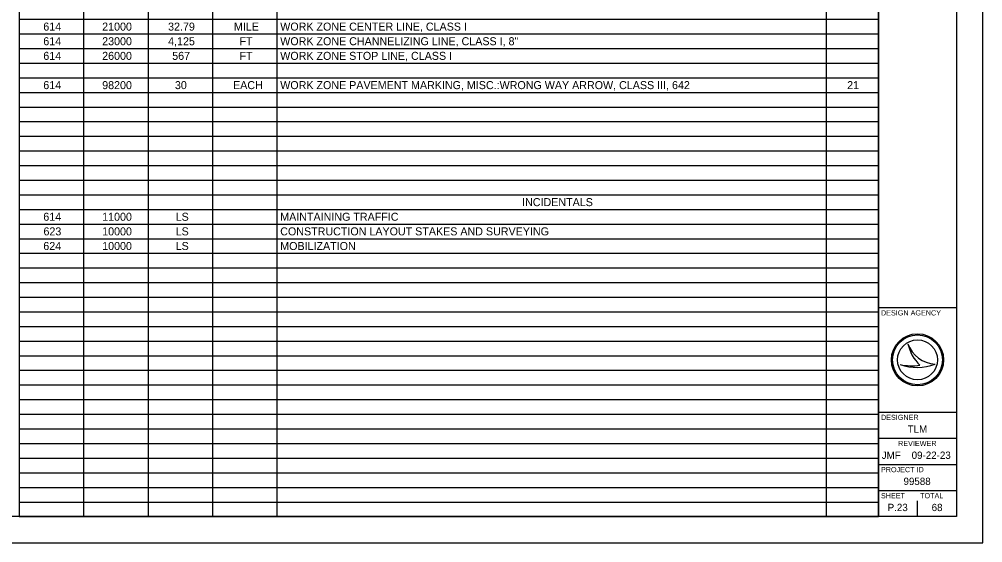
# Model space of a CAD drawing. Extents: x 0 to 34, y 0 to 22.
# Drawn here: x 15.54 to 34, y 0 to 10.02 of the extents above; entities that cross this region are included whole.
import ezdxf

# ---------------------------------------------------------------- set-up
doc = ezdxf.new("R2010")
doc.units = 0
for name, color, linetype in [('SH_Border', 7, 'Continuous'), ('SH_Cut_Line', 7, 'Continuous'), ('SH_Data', 7, 'Continuous'), ('SH_Text', 7, 'Continuous')]:
    doc.layers.add(name, color=color, linetype=linetype)

msp = doc.modelspace()

# ---------------------------------------------------------------- linework, layer by layer
at = {"layer": 'SH_Border'}
for p, q in [((32, 0.5), (32, 21.5)), ((32, 4.5), (33.5, 4.5)), ((32, 2.5), (33.5, 2.5)), ((32, 2), (33.5, 2)), ((32, 1.5), (33.5, 1.5)), ((32, 1), (33.5, 1))]:
    msp.add_line(p, q, dxfattribs=at)
msp.add_lwpolyline([(1.5, 21.5), (33.5, 21.5), (33.5, 0.5), (1.5, 0.5)], close=True, dxfattribs=at)
at = {"layer": 'SH_Cut_Line'}
msp.add_lwpolyline([(0, 0), (34, 0), (34, 22), (0, 22)], close=True, dxfattribs=at)
at = {"layer": 'SH_Data'}
for p, q in [((32.567, 3.81), (32.567, 3.81)), ((32.417, 3.41), (32.417, 3.41)), ((32.75, 3.5), (32.75, 3.5)), ((33.087, 3.419), (33.087, 3.419)), ((32.75, 0.5), (32.75, 0.8)), ((32.375, 0.675), (32.375, 0.675))]:
    msp.add_line(p, q, dxfattribs=at)
for radius in [0.5, 0.477, 0.477, 0.382]:
    msp.add_circle((32.75, 3.5), radius, dxfattribs=at)
for centre, radius, start, end in [((33.116, 3.998), 0.58, 198.9257, 198.9319), ((33.347, 3.97), 0.796, 191.6379, 191.6421), ((33.116, 3.998), 0.58, 198.9319, 267.1657), ((33.347, 3.97), 0.796, 191.6421, 226.0947), ((32.739, 4.37), 1.013, 251.4576, 290.0832), ((32.648, 4.654), 1.266, 259.4964, 259.4995), ((32.739, 4.37), 1.013, 251.4527, 251.4576), ((32.648, 4.654), 1.266, 259.4995, 276.6672)]:
    msp.add_arc(centre, radius, start, end, dxfattribs=at)
at = {"layer": 'SH_Text'}
for p, q in [((15.537, 10.3), (15.537, 10.02)), ((16.771, 10.3), (16.771, 10.02)), ((18.005, 10.3), (18.005, 10.02)), ((19.239, 10.3), (19.239, 10.02)), ((20.473, 10.3), (20.473, 10.02)), ((31.001, 10.3), (31.001, 10.02)), ((32.004, 10.3), (32.004, 10.02)), ((15.537, 10.02), (18.005, 10.02)), ((15.537, 10.02), (15.537, 9.74)), ((16.771, 10.02), (16.771, 9.74)), ((18.005, 10.02), (19.239, 10.02)), ((18.005, 10.02), (18.005, 9.74)), ((19.239, 10.02), (32.004, 10.02)), ((19.239, 10.02), (19.239, 9.74)), ((20.473, 10.02), (20.473, 9.74)), ((31.001, 10.02), (31.001, 9.74)), ((32.004, 10.02), (32.004, 9.74)), ((15.537, 9.74), (18.005, 9.74)), ((15.537, 9.74), (15.537, 8.9)), ((16.771, 9.74), (16.771, 8.9)), ((18.005, 9.74), (19.239, 9.74)), ((18.005, 9.74), (18.005, 8.9)), ((19.239, 9.74), (32.004, 9.74)), ((19.239, 9.74), (19.239, 8.9)), ((20.473, 9.74), (20.473, 8.9)), ((31.001, 9.74), (31.001, 8.9)), ((32.004, 9.74), (32.004, 8.9)), ((15.537, 9.46), (18.005, 9.46)), ((18.005, 9.46), (19.239, 9.46)), ((19.239, 9.46), (32.004, 9.46)), ((15.537, 9.18), (18.005, 9.18)), ((18.005, 9.18), (19.239, 9.18)), ((19.239, 9.18), (32.004, 9.18)), ((15.537, 8.9), (18.005, 8.9)), ((15.537, 8.9), (15.537, 8.34)), ((16.771, 8.9), (16.771, 8.34)), ((18.005, 8.9), (19.239, 8.9)), ((18.005, 8.9), (18.005, 8.34)), ((19.239, 8.9), (32.004, 8.9)), ((19.239, 8.9), (19.239, 8.34)), ((20.473, 8.9), (20.473, 8.34)), ((31.001, 8.9), (31.001, 8.34)), ((32.004, 8.9), (32.004, 8.34)), ((15.537, 8.62), (18.005, 8.62)), ((18.005, 8.62), (19.239, 8.62)), ((19.239, 8.62), (32.004, 8.62)), ((15.537, 8.34), (18.005, 8.34)), ((15.537, 8.34), (15.537, 7.5)), ((16.771, 8.34), (16.771, 7.5)), ((18.005, 8.34), (19.239, 8.34)), ((18.005, 8.34), (18.005, 7.5)), ((19.239, 8.34), (32.004, 8.34)), ((19.239, 8.34), (19.239, 7.5)), ((20.473, 8.34), (20.473, 7.5)), ((31.001, 8.34), (31.001, 7.5)), ((32.004, 8.34), (32.004, 7.5)), ((15.537, 8.06), (18.005, 8.06)), ((18.005, 8.06), (19.239, 8.06)), ((19.239, 8.06), (32.004, 8.06)), ((15.537, 7.78), (18.005, 7.78)), ((18.005, 7.78), (19.239, 7.78)), ((19.239, 7.78), (32.004, 7.78)), ((15.537, 7.5), (18.005, 7.5)), ((15.537, 7.5), (15.537, 6.94)), ((16.771, 7.5), (16.771, 6.94)), ((18.005, 7.5), (19.239, 7.5)), ((18.005, 7.5), (18.005, 6.94)), ((19.239, 7.5), (32.004, 7.5)), ((19.239, 7.5), (19.239, 6.94)), ((20.473, 7.5), (20.473, 6.94)), ((31.001, 7.5), (31.001, 6.94)), ((32.004, 7.5), (32.004, 6.94)), ((15.537, 7.22), (18.005, 7.22)), ((18.005, 7.22), (19.239, 7.22)), ((19.239, 7.22), (32.004, 7.22)), ((15.537, 6.94), (18.005, 6.94)), ((15.537, 6.94), (15.537, 6.1)), ((16.771, 6.94), (16.771, 6.1)), ((18.005, 6.94), (19.239, 6.94)), ((18.005, 6.94), (18.005, 6.1)), ((19.239, 6.94), (32.004, 6.94)), ((19.239, 6.94), (19.239, 6.1)), ((20.473, 6.94), (20.473, 6.1)), ((31.001, 6.94), (31.001, 6.1)), ((32.004, 6.94), (32.004, 6.1)), ((15.537, 6.66), (18.005, 6.66)), ((18.005, 6.66), (19.239, 6.66)), ((19.239, 6.66), (32.004, 6.66)), ((15.537, 6.38), (18.005, 6.38)), ((18.005, 6.38), (19.239, 6.38)), ((19.239, 6.38), (32.004, 6.38)), ((15.537, 6.1), (18.005, 6.1)), ((15.537, 6.1), (15.537, 4.98)), ((16.771, 6.1), (16.771, 4.98)), ((18.005, 6.1), (19.239, 6.1)), ((18.005, 6.1), (18.005, 4.98)), ((19.239, 6.1), (32.004, 6.1)), ((19.239, 6.1), (19.239, 4.98)), ((20.473, 6.1), (20.473, 4.98)), ((31.001, 6.1), (31.001, 4.98)), ((32.004, 6.1), (32.004, 4.98)), ((15.537, 5.82), (18.005, 5.82)), ((18.005, 5.82), (19.239, 5.82)), ((19.239, 5.82), (32.004, 5.82)), ((15.537, 5.54), (18.005, 5.54)), ((18.005, 5.54), (19.239, 5.54)), ((19.239, 5.54), (32.004, 5.54)), ((15.537, 5.26), (18.005, 5.26)), ((18.005, 5.26), (19.239, 5.26)), ((19.239, 5.26), (32.004, 5.26)), ((15.537, 4.98), (18.005, 4.98)), ((15.537, 4.98), (15.537, 4.7)), ((16.771, 4.98), (16.771, 4.7)), ((18.005, 4.98), (19.239, 4.98)), ((18.005, 4.98), (18.005, 4.7)), ((19.239, 4.98), (32.004, 4.98)), ((19.239, 4.98), (19.239, 4.7)), ((20.473, 4.98), (20.473, 4.7)), ((31.001, 4.98), (31.001, 4.7)), ((32.004, 4.98), (32.004, 4.7)), ((15.537, 4.7), (18.005, 4.7)), ((15.537, 4.7), (15.537, 3.58)), ((16.771, 4.7), (16.771, 3.58)), ((18.005, 4.7), (19.239, 4.7)), ((18.005, 4.7), (18.005, 3.58)), ((19.239, 4.7), (32.004, 4.7)), ((19.239, 4.7), (19.239, 3.58)), ((20.473, 4.7), (20.473, 3.58)), ((31.001, 4.7), (31.001, 3.58)), ((32.004, 4.7), (32.004, 3.58)), ((15.537, 4.42), (18.005, 4.42)), ((18.005, 4.42), (19.239, 4.42)), ((19.239, 4.42), (32.004, 4.42)), ((15.537, 4.14), (18.005, 4.14)), ((18.005, 4.14), (19.239, 4.14)), ((19.239, 4.14), (32.004, 4.14)), ((15.537, 3.86), (18.005, 3.86)), ((18.005, 3.86), (19.239, 3.86)), ((19.239, 3.86), (32.004, 3.86)), ((15.537, 3.58), (18.005, 3.58)), ((15.537, 3.58), (15.537, 3.3)), ((16.771, 3.58), (16.771, 3.3)), ((18.005, 3.58), (19.239, 3.58)), ((18.005, 3.58), (18.005, 3.3)), ((19.239, 3.58), (32.004, 3.58)), ((19.239, 3.58), (19.239, 3.3)), ((20.473, 3.58), (20.473, 3.3)), ((31.001, 3.58), (31.001, 3.3)), ((32.004, 3.58), (32.004, 3.3)), ((15.537, 3.3), (18.005, 3.3)), ((15.537, 3.3), (15.537, 2.179)), ((16.771, 3.3), (16.771, 2.179)), ((18.005, 3.3), (19.239, 3.3)), ((18.005, 3.3), (18.005, 2.179)), ((19.239, 3.3), (32.004, 3.3)), ((19.239, 3.3), (19.239, 2.179)), ((20.473, 3.3), (20.473, 2.179)), ((31.001, 3.3), (31.001, 2.179)), ((32.004, 3.3), (32.004, 2.179)), ((15.537, 3.02), (18.005, 3.02)), ((18.005, 3.02), (19.239, 3.02)), ((19.239, 3.02), (32.004, 3.02)), ((15.537, 2.74), (18.005, 2.74)), ((18.005, 2.74), (19.239, 2.74)), ((19.239, 2.74), (32.004, 2.74)), ((15.537, 2.46), (18.005, 2.46)), ((18.005, 2.46), (19.239, 2.46)), ((19.239, 2.46), (32.004, 2.46)), ((15.537, 2.179), (18.005, 2.179)), ((15.537, 2.179), (15.537, 1.899)), ((16.771, 2.179), (16.771, 1.899)), ((18.005, 2.179), (19.239, 2.179)), ((18.005, 2.179), (18.005, 1.899)), ((19.239, 2.179), (32.004, 2.179)), ((19.239, 2.179), (19.239, 1.899)), ((20.473, 2.179), (20.473, 1.899)), ((31.001, 2.179), (31.001, 1.899)), ((32.004, 2.179), (32.004, 1.899)), ((15.537, 1.899), (18.005, 1.899)), ((15.537, 1.899), (15.537, 0.779)), ((16.771, 1.899), (16.771, 0.779)), ((18.005, 1.899), (19.239, 1.899)), ((18.005, 1.899), (18.005, 0.779)), ((19.239, 1.899), (32.004, 1.899)), ((19.239, 1.899), (19.239, 0.779)), ((20.473, 1.899), (20.473, 0.779)), ((31.001, 1.899), (31.001, 0.779)), ((32.004, 1.899), (32.004, 0.779)), ((15.537, 1.619), (18.005, 1.619)), ((18.005, 1.619), (19.239, 1.619)), ((19.239, 1.619), (32.004, 1.619)), ((15.537, 1.339), (18.005, 1.339)), ((18.005, 1.339), (19.239, 1.339)), ((19.239, 1.339), (32.004, 1.339)), ((15.537, 1.059), (18.005, 1.059)), ((18.005, 1.059), (19.239, 1.059)), ((19.239, 1.059), (32.004, 1.059)), ((15.537, 0.779), (18.005, 0.779)), ((15.537, 0.779), (15.537, 0.499)), ((16.771, 0.779), (16.771, 0.499)), ((18.005, 0.779), (19.239, 0.779)), ((18.005, 0.779), (18.005, 0.499)), ((19.239, 0.779), (32.004, 0.779)), ((19.239, 0.779), (19.239, 0.499)), ((20.473, 0.779), (20.473, 0.499)), ((31.001, 0.779), (31.001, 0.499)), ((32.004, 0.779), (32.004, 0.499)), ((15.537, 0.499), (18.005, 0.499)), ((18.005, 0.499), (19.239, 0.499)), ((19.239, 0.499), (32.004, 0.499))]:
    msp.add_line(p, q, dxfattribs=at)

# ---------------------------------------------------------------- texts
at = {"layer": 'SH_Data'}
for s, height, p in [('DESIGN AGENCY', 0.1, (32.05, 4.35)), ('DESIGNER', 0.1, (32.05, 2.35)), ('TLM', 0.14, (32.562, 2.105)), ('REVIEWER', 0.1, (32.378, 1.85)), ('JMF', 0.14, (32.064, 1.605)), ('09-22-23', 0.14, (32.638, 1.605)), ('PROJECT ID', 0.1, (32.05, 1.35)), ('99588', 0.14, (32.482, 1.105)), ('SHEET', 0.1, (32.05, 0.85)), ('TOTAL', 0.1, (32.8, 0.85)), ('P.23', 0.14, (32.178, 0.605)), ('68', 0.14, (33.021, 0.605))]:
    msp.add_text(s, height=height, dxfattribs=at).set_placement(p)
at = {"layer": 'SH_Text'}
for s, height, p in [('614', 0.1533, (15.998, 9.803)), ('21000', 0.1533, (17.126, 9.803)), ('32.79', 0.1533, (18.389, 9.803)), ('MILE', 0.1533, (19.651, 9.803)), ('WORK ZONE CENTER LINE, CLASS I', 0.15334, (20.538, 9.803)), ('614', 0.1533, (15.998, 9.523)), ('23000', 0.1533, (17.126, 9.523)), ('4,125', 0.1533, (18.39, 9.523)), ('FT', 0.1533, (19.758, 9.523)), ('WORK ZONE CHANNELIZING LINE, CLASS I, 8"', 0.15334, (20.538, 9.523)), ('614', 0.1533, (15.998, 9.243)), ('26000', 0.1533, (17.126, 9.243)), ('567', 0.1533, (18.468, 9.243)), ('FT', 0.1533, (19.758, 9.243)), ('WORK ZONE STOP LINE, CLASS I', 0.15334, (20.538, 9.243)), ('614', 0.1533, (15.998, 8.683)), ('98200', 0.1533, (17.126, 8.683)), ('30', 0.1533, (18.52, 8.683)), ('EACH', 0.1533, (19.634, 8.683)), ('WORK ZONE PAVEMENT MARKING, MISC.:WRONG WAY ARROW, CLASS III, 642', 0.15334, (20.538, 8.683)), ('21', 0.1533, (31.402, 8.683)), ('INCIDENTALS', 0.15334, (25.173, 6.443)), ('614', 0.1533, (15.998, 6.163)), ('11000', 0.1533, (17.126, 6.163)), ('LS', 0.1533, (18.534, 6.163)), ('MAINTAINING TRAFFIC', 0.15334, (20.538, 6.163)), ('623', 0.1533, (16.001, 5.883)), ('10000', 0.1533, (17.126, 5.883)), ('LS', 0.1533, (18.534, 5.883)), ('CONSTRUCTION LAYOUT STAKES AND SURVEYING', 0.15334, (20.538, 5.883)), ('624', 0.1533, (15.998, 5.603)), ('10000', 0.1533, (17.126, 5.603)), ('LS', 0.1533, (18.534, 5.603)), ('MOBILIZATION', 0.15334, (20.538, 5.603))]:
    msp.add_text(s, height=height, dxfattribs=at).set_placement(p)

doc.saveas('drawing.dxf')
